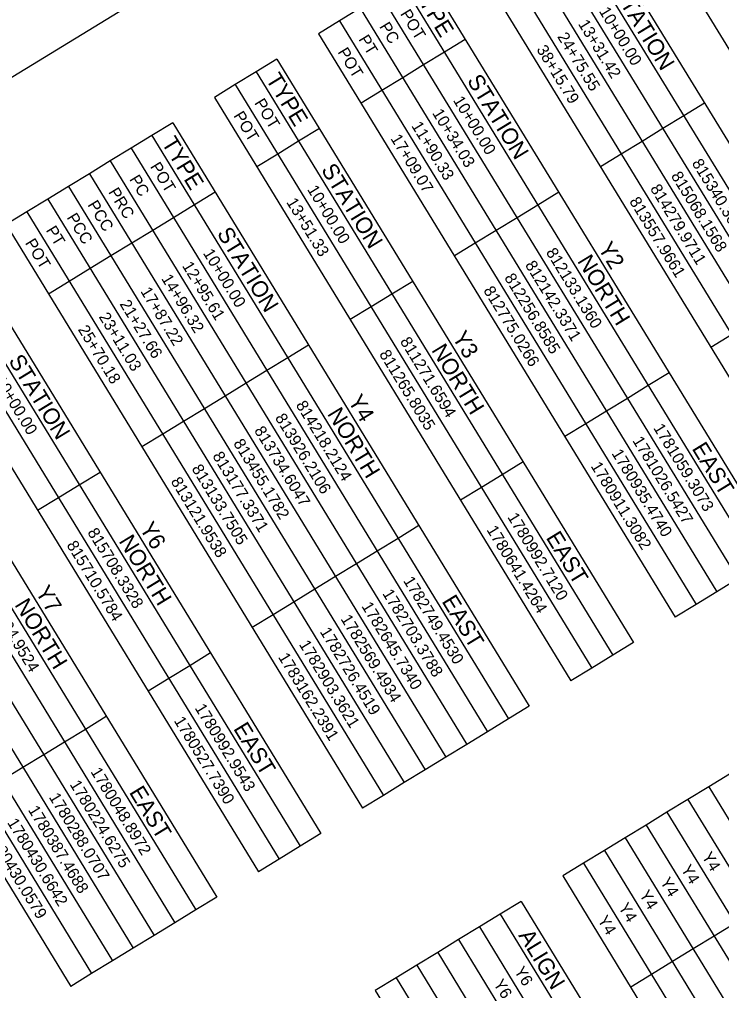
# Model space of a CAD drawing. Extents: x 1753086 to 1770987, y 792577 to 812636.
# Drawn here: x 1756968 to 1759624, y 804785 to 808460 of the extents above; entities that cross this region are included whole.
import ezdxf

# ---------------------------------------------------------------- set-up
doc = ezdxf.new("R2010")
doc.units = 0
for name, color, linetype in [('CTL Sheet Border CELL', 7, 'Continuous'), ('CTL Sheet Notes CELL', 7, 'Continuous'), ('CTL Sheet Table Cell', 7, 'Continuous'), ('CTL Sheet Text', 7, 'Continuous')]:
    doc.layers.add(name, color=color, linetype=linetype)

msp = doc.modelspace()

# ---------------------------------------------------------------- linework, layer by layer
at = {"layer": 'CTL Sheet Border CELL'}
msp.add_lwpolyline([(1770671.7, 798289.4), (1762511, 811645.8), (1753161.6, 805933.4), (1761322.3, 792577)], close=True, dxfattribs=at)
at = {"layer": 'CTL Sheet Table Cell'}
for p, q in [((1759203.6, 809080.1), (1760552.5, 806872.4)), ((1759045.9, 808983.7), (1760394.8, 806776)), ((1758967.1, 808935.5), (1760316, 806727.8)), ((1758888.2, 808887.4), (1760237.1, 806679.7)), ((1758809.4, 808839.2), (1760158.3, 806631.5)), ((1758730.5, 808791), (1760079.4, 806583.3)), ((1758651.7, 808742.8), (1760000.6, 806535.1)), ((1758494, 808646.5), (1759842.9, 806438.8)), ((1758415.1, 808598.3), (1759764.1, 806390.6)), ((1758336.3, 808550.1), (1759685.2, 806342.4)), ((1758257.4, 808502), (1758178.6, 808453.8)), ((1758257.4, 808502), (1759606.4, 806294.2)), ((1758178.6, 808453.8), (1758099.7, 808405.6)), ((1758178.6, 808453.8), (1759527.5, 806246.1)), ((1758099.7, 808405.6), (1759448.7, 806197.9)), ((1758654.6, 808383.7), (1758575.7, 808335.5)), ((1758575.7, 808335.5), (1758496.9, 808287.3)), ((1757942.1, 808309.3), (1757863.2, 808261.1)), ((1757942.1, 808309.3), (1759291, 806101.5)), ((1758496.9, 808287.3), (1758418, 808239.1)), ((1757863.2, 808261.1), (1757784.4, 808212.9)), ((1757863.2, 808261.1), (1759212.1, 806053.4)), ((1757784.4, 808212.9), (1757705.5, 808164.7)), ((1757784.4, 808212.9), (1759133.3, 806005.2)), ((1758418, 808239.1), (1758339.2, 808191)), ((1758339.2, 808191), (1758260.3, 808142.8)), ((1757705.5, 808164.7), (1759054.4, 805957)), ((1759559.8, 808142.7), (1759480.9, 808094.5)), ((1757547.8, 808068.4), (1757469, 808020.2)), ((1757547.8, 808068.4), (1758896.7, 805860.7)), ((1759480.9, 808094.5), (1759402.1, 808046.3)), ((1758102.6, 808046.4), (1758023.8, 807998.3)), ((1759402.1, 808046.3), (1759323.2, 807998.2)), ((1757469, 808020.2), (1757390.1, 807972)), ((1757469, 808020.2), (1758817.9, 805812.5)), ((1758023.8, 807998.3), (1757944.9, 807950.1)), ((1759323.2, 807998.2), (1759244.4, 807950)), ((1757390.1, 807972), (1757311.3, 807923.9)), ((1757390.1, 807972), (1758739, 805764.3)), ((1757311.3, 807923.9), (1757232.4, 807875.7)), ((1757311.3, 807923.9), (1758660.2, 805716.1)), ((1757944.9, 807950.1), (1757866.1, 807901.9)), ((1759244.4, 807950), (1759165.5, 807901.8)), ((1757232.4, 807875.7), (1757153.6, 807827.5)), ((1757232.4, 807875.7), (1758581.3, 805668)), ((1757153.6, 807827.5), (1757074.7, 807779.3)), ((1757153.6, 807827.5), (1758502.5, 805619.8)), ((1757708.4, 807805.6), (1757629.6, 807757.4)), ((1759007.9, 807805.5), (1758929, 807757.3)), ((1757074.7, 807779.3), (1756995.9, 807731.2)), ((1757074.7, 807779.3), (1758423.7, 805571.6)), ((1756995.9, 807731.2), (1756917, 807683)), ((1756995.9, 807731.2), (1758344.8, 805523.4)), ((1757629.6, 807757.4), (1757550.7, 807709.2)), ((1758929, 807757.3), (1758850.2, 807709.1)), ((1757550.7, 807709.2), (1757471.9, 807661)), ((1758850.2, 807709.1), (1758771.3, 807660.9)), ((1756917, 807683), (1758266, 805475.3)), ((1757471.9, 807661), (1757393, 807612.9)), ((1758771.3, 807660.9), (1758692.5, 807612.8)), ((1756759.3, 807586.6), (1758108.3, 805378.9)), ((1757393, 807612.9), (1757314.2, 807564.7)), ((1758692.5, 807612.8), (1758613.6, 807564.6)), ((1757314.2, 807564.7), (1757235.3, 807516.5)), ((1756680.5, 807538.5), (1758029.4, 805330.7)), ((1757235.3, 807516.5), (1757156.5, 807468.3)), ((1756601.7, 807490.3), (1757950.6, 805282.6)), ((1756522.8, 807442.1), (1757871.7, 805234.4)), ((1757156.5, 807468.3), (1757077.6, 807420.2)), ((1758455.9, 807468.2), (1758377.1, 807420.1)), ((1758377.1, 807420.1), (1758298.2, 807371.9)), ((1758298.2, 807371.9), (1758219.4, 807323.7)), ((1756365.1, 807345.8), (1757714, 805138)), ((1756286.3, 807297.6), (1757635.2, 805089.9)), ((1759661.9, 807266.6), (1759583.1, 807218.5)), ((1756207.4, 807249.4), (1757556.3, 805041.7)), ((1758061.7, 807227.4), (1757982.8, 807179.2)), ((1756128.6, 807201.2), (1757477.5, 804993.5)), ((1757982.8, 807179.2), (1757904, 807131)), ((1756049.7, 807153), (1757398.6, 804945.3)), ((1757904, 807131), (1757825.1, 807082.8)), ((1759425.4, 807122.1), (1759346.5, 807073.9)), ((1755970.9, 807104.9), (1757319.8, 804897.2)), ((1757825.1, 807082.8), (1757746.3, 807034.6)), ((1759346.5, 807073.9), (1759267.7, 807025.8)), ((1755892, 807056.7), (1757240.9, 804849)), ((1757746.3, 807034.6), (1757667.5, 806986.5)), ((1755813.2, 807008.5), (1757162.1, 804800.8)), ((1759267.7, 807025.8), (1759188.8, 806977.6)), ((1757667.5, 806986.5), (1757588.6, 806938.3)), ((1759188.8, 806977.6), (1759110, 806929.4)), ((1757588.6, 806938.3), (1757509.8, 806890.1)), ((1759110, 806929.4), (1759031.1, 806881.2)), ((1757509.8, 806890.1), (1757430.9, 806841.9)), ((1758873.4, 806784.9), (1758794.6, 806736.7)), ((1757273.2, 806745.6), (1757194.4, 806697.4)), ((1758794.6, 806736.7), (1758715.8, 806688.5)), ((1757194.4, 806697.4), (1757115.5, 806649.2)), ((1758715.8, 806688.5), (1758636.9, 806640.4)), ((1757115.5, 806649.2), (1757036.7, 806601.1)), ((1758479.2, 806544), (1758400.4, 806495.8)), ((1758400.4, 806495.8), (1758321.5, 806447.7)), ((1758321.5, 806447.7), (1758242.7, 806399.5)), ((1758242.7, 806399.5), (1758163.8, 806351.3)), ((1758163.8, 806351.3), (1758085, 806303.1)), ((1759685.2, 806342.4), (1759606.4, 806294.2)), ((1758085, 806303.1), (1758006.1, 806255)), ((1759606.4, 806294.2), (1759527.5, 806246.1)), ((1758006.1, 806255), (1757927.3, 806206.8)), ((1759527.5, 806246.1), (1759448.7, 806197.9)), ((1757927.3, 806206.8), (1757848.4, 806158.6)), ((1759291, 806101.5), (1759212.1, 806053.4)), ((1757690.7, 806062.3), (1757611.9, 806014.1)), ((1759212.1, 806053.4), (1759133.3, 806005.2)), ((1757611.9, 806014.1), (1757533, 805965.9)), ((1759133.3, 806005.2), (1759054.4, 805957)), ((1757533, 805965.9), (1757454.2, 805917.7)), ((1758896.7, 805860.7), (1758817.9, 805812.5)), ((1757296.5, 805821.4), (1757217.7, 805773.2)), ((1758817.9, 805812.5), (1758739, 805764.3)), ((1757217.7, 805773.2), (1757138.8, 805725)), ((1758739, 805764.3), (1758660.2, 805716.1)), ((1757138.8, 805725), (1757060, 805676.8)), ((1758660.2, 805716.1), (1758581.3, 805668)), ((1757060, 805676.8), (1756981.1, 805628.7)), ((1758581.3, 805668), (1758502.5, 805619.8)), ((1756981.1, 805628.7), (1756902.3, 805580.5)), ((1758502.5, 805619.8), (1758423.7, 805571.6)), ((1759654.1, 805603.9), (1759575.3, 805555.7)), ((1758423.7, 805571.6), (1758344.8, 805523.4)), ((1759575.3, 805555.7), (1759496.4, 805507.5)), ((1759575.3, 805555.7), (1761373.8, 802612.1)), ((1758344.8, 805523.4), (1758266, 805475.3)), ((1759496.4, 805507.5), (1759417.6, 805459.3)), ((1759496.4, 805507.5), (1761295, 802563.9)), ((1759417.6, 805459.3), (1759338.7, 805411.2)), ((1759417.6, 805459.3), (1761216.1, 802515.7)), ((1758108.3, 805378.9), (1758029.4, 805330.7)), ((1759338.7, 805411.2), (1759259.9, 805363)), ((1759338.7, 805411.2), (1761137.3, 802467.5)), ((1759259.9, 805363), (1759181, 805314.8)), ((1759259.9, 805363), (1761058.4, 802419.4)), ((1758029.4, 805330.7), (1757950.6, 805282.6)), ((1759181, 805314.8), (1759102.2, 805266.6)), ((1759181, 805314.8), (1760979.6, 802371.2)), ((1757950.6, 805282.6), (1757871.7, 805234.4)), ((1759102.2, 805266.6), (1759023.3, 805218.5)), ((1759102.2, 805266.6), (1760900.7, 802323)), ((1759023.3, 805218.5), (1760821.9, 802274.8)), ((1757714, 805138), (1757635.2, 805089.9)), ((1758865.6, 805122.1), (1758786.8, 805073.9)), ((1758865.6, 805122.1), (1760664.2, 802178.5)), ((1757635.2, 805089.9), (1757556.3, 805041.7)), ((1758786.8, 805073.9), (1758707.9, 805025.8)), ((1758786.8, 805073.9), (1760585.4, 802130.3)), ((1757556.3, 805041.7), (1757477.5, 804993.5)), ((1758707.9, 805025.8), (1758629.1, 804977.6)), ((1758707.9, 805025.8), (1760506.5, 802082.1)), ((1759674.5, 805038.8), (1759595.7, 804990.6)), ((1757477.5, 804993.5), (1757398.6, 804945.3)), ((1758629.1, 804977.6), (1758550.3, 804929.4)), ((1758629.1, 804977.6), (1760427.7, 802034)), ((1759595.7, 804990.6), (1759516.8, 804942.5)), ((1757398.6, 804945.3), (1757319.8, 804897.2)), ((1759516.8, 804942.5), (1759438, 804894.3)), ((1758550.3, 804929.4), (1758471.4, 804881.2)), ((1758550.3, 804929.4), (1760348.8, 801985.8)), ((1757319.8, 804897.2), (1757240.9, 804849)), ((1758471.4, 804881.2), (1758392.6, 804833.1)), ((1758471.4, 804881.2), (1760270, 801937.6)), ((1759438, 804894.3), (1759359.1, 804846.1)), ((1757240.9, 804849), (1757162.1, 804800.8)), ((1758392.6, 804833.1), (1758313.7, 804784.9)), ((1758392.6, 804833.1), (1760191.1, 801889.4)), ((1759359.1, 804846.1), (1759280.3, 804797.9)), ((1758313.7, 804784.9), (1760112.3, 801841.3))]:
    msp.add_line(p, q, dxfattribs=at)

# ---------------------------------------------------------------- texts
at = {"layer": 'CTL Sheet Notes CELL'}
for s, p in [('TYPE', (1758450.2, 808570.5)), ('STATION', (1759211.2, 808565.5)), ('TYPE', (1757898.2, 808233.3)), ('STATION', (1758659.3, 808228.3)), ('TYPE', (1757504, 807992.4)), ('STATION', (1758107.4, 807891)), ('STATION', (1757713.1, 807650.1)), ('Y2', (1759155, 807594.1)), ('NORTH', (1759076.6, 807545.3)), ('Y3', (1758603.1, 807256.9)), ('NORTH', (1758524.6, 807208.1)), ('STATION', (1756924.7, 807168.4)), ('Y4', (1758208.9, 807016)), ('NORTH', (1758130.4, 806967.2)), ('EAST', (1759510, 806835.9)), ('Y6', (1757420.4, 806534.3)), ('EAST', (1758958.1, 806498.7)), ('NORTH', (1757341.9, 806485.5)), ('Y7', (1757026.2, 806293.4)), ('NORTH', (1756947.7, 806244.6)), ('EAST', (1758563.8, 806257.8)), ('EAST', (1757775.4, 805776)), ('EAST', (1757381.1, 805535.2)), ('ALIGN', (1758854.1, 804993.4))]:
    msp.add_text(s, height=61.6, rotation=301.4249, dxfattribs=at).set_placement(p)
at = {"layer": 'CTL Sheet Text'}
for s, p in [('10+00.00', (1759158.9, 808490.9)), ('POT', (1758406.9, 808481)), ('PC ', (1758328, 808432.8)), ('13+31.42', (1759080, 808442.7)), ('PT ', (1758249.2, 808384.7)), ('24+75.55', (1759001.2, 808394.5)), ('POT', (1758170.3, 808336.5)), ('38+15.79', (1758922.3, 808346.3)), ('POT', (1757855, 808143.8)), ('10+00.00', (1758606.9, 808153.6)), ('POT', (1757776.1, 808095.6)), ('10+34.03', (1758528.1, 808105.4)), ('11+90.33', (1758449.2, 808057.3)), ('17+09.07', (1758370.4, 808009.1)), ('POT', (1757460.7, 807902.9)), ('815340.3045', (1759510.1, 807916)), ('815068.1568', (1759431.3, 807867.8)), ('PC ', (1757381.9, 807854.7)), ('PRC', (1757303, 807806.6)), ('10+00.00', (1758055, 807816.4)), ('814279.9711', (1759352.4, 807819.6)), ('PCC', (1757224.2, 807758.4)), ('13+51.33', (1757976.1, 807768.2)), ('813557.9661', (1759273.6, 807771.4)), ('PCC', (1757145.3, 807710.2)), ('PT ', (1757066.5, 807662)), ('POT', (1756987.6, 807613.9)), ('10+00.00', (1757660.8, 807575.5)), ('812133.1360', (1758958.2, 807578.7)), ('812142.3371', (1758879.3, 807530.5)), ('12+95.61', (1757581.9, 807527.3)), ('14+96.32', (1757503.1, 807479.2)), ('812256.8585', (1758800.5, 807482.4)), ('17+87.22', (1757424.2, 807431)), ('812775.0266', (1758721.6, 807434.2)), ('21+27.66', (1757345.4, 807382.8)), ('23+11.03', (1757266.5, 807334.6)), ('25+70.18', (1757187.7, 807286.5)), ('811271.6594', (1758406.3, 807241.5)), ('811265.8035', (1758327.4, 807193.3)), ('10+00.00', (1756872.3, 807093.8)), ('814218.2124', (1758012, 807000.6)), ('813926.2106', (1757933.2, 806952.4)), ('1781059.3073', (1759364.3, 806914)), ('813734.6047', (1757854.3, 806904.3)), ('813455.1782', (1757775.5, 806856.1)), ('1781026.5427', (1759285.5, 806865.8)), ('813177.3371', (1757696.6, 806807.9)), ('1780935.4740', (1759206.6, 806817.7)), ('813133.7505', (1757617.8, 806759.7)), ('1780911.3082', (1759127.8, 806769.5)), ('813121.9538', (1757538.9, 806711.6)), ('1780992.7120', (1758812.4, 806576.8)), ('815708.3328', (1757223.5, 806518.9)), ('1780641.4264', (1758733.6, 806528.6)), ('815710.5784', (1757144.7, 806470.7)), ('1782749.4530', (1758418.2, 806335.9)), ('1782703.3788', (1758339.3, 806287.7)), ('815704.9524', (1756829.3, 806278)), ('1782645.7340', (1758260.5, 806239.5)), ('1782569.4934', (1758181.6, 806191.4)), ('1782726.4519', (1758102.8, 806143.2)), ('1782903.3621', (1758023.9, 806095)), ('1783162.2391', (1757945.1, 806046.8)), ('1780992.9543', (1757629.7, 805854.1)), ('1780527.7390', (1757550.8, 805806)), ('1780048.8972', (1757235.5, 805613.3)), ('1780224.6275', (1757156.6, 805565.1)), ('1780288.0707', (1757077.8, 805516.9)), ('1780387.4688', (1756998.9, 805468.7)), ('1780430.6642', (1756920.1, 805420.6)), ('1780430.0579', (1756841.2, 805372.4)), ('Y4', (1759547.7, 805292.7)), ('Y4', (1759468.9, 805244.6)), ('Y4', (1759390, 805196.4)), ('Y4', (1759311.2, 805148.2)), ('Y4', (1759232.3, 805100)), ('Y4', (1759153.5, 805051.9)), ('Y6', (1758838.1, 804859.2)), ('Y6', (1758759.3, 804811))]:
    msp.add_text(s, height=44, rotation=301.4249, dxfattribs=at).set_placement(p)

doc.saveas('drawing.dxf')
